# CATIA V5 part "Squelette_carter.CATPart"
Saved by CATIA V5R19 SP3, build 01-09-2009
Part number: Squelette_carter
Bounding box of the stored display mesh (mm): x 0 to 0, y -10 to 300, z -104 to 10
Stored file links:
  C:\Users\Frédéric\Documents\WF\STSCPI 09-11\Projets\Projet multiplicateur eolienne\Maquette eolienne\Squelette_carter.CATPart
  C:\Users\Frédéric\Documents\WF\STSCPI 09-11\Projets\Projet multiplicateur eolienne\Maquette eolienne\Squelette_sortie.CATPart
  C:\Users\Frédéric\Documents\WF\STSCPI 09-11\Projets\Projet multiplicateur eolienne\Maquette eolienne\Squelette_intermediaire.CATPart
  C:\Users\Frédéric\Documents\WF\STSCPI 09-11\Projets\Projet multiplicateur eolienne\Maquette eolienne\Multiplicateur_eolien.CATProduct
  C:\Users\Frédéric\Documents\WF\STSCPI 09-11\Projets\Projet multiplicateur eolienne\Maquette eolienne\Squelette_entree.CATPart
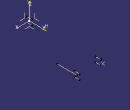
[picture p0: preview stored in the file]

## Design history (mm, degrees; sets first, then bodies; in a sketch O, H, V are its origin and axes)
External parameters (linked from other documents)
  External.Longueur = 18 mm
  External.Longueur.1 = 76 mm
  `External.rayon primitif A et C` = 76 mm
  `External.rayon primitif B et D` = 18 mm
  External.Longueur.2 = 20 mm
AxisSystem1: origin (0, 0, 0), X (1, 0, 0), Y (0, 1, 0), Z (0, 0, 1)
Body1 (main body)
  Sketch1 on YZ plane of AxisSystem1, origin (0, 0, 0), H (0, 1, 0), V (0, 0, 1)
    line L1 (-10, 10) -> (10, 10)
    point P1 (-10, 10)
    line L2 (-10, -10) -> (10, -10)
    point P3 (-10, -10)
    line L3 (270, 10) -> (290, 10)
    point P5 (270, 10)
    line L4 (270, -10) -> (290, -10)
    point P7 (270, -10)
    point P9 (280, 0)
    point P10 (193.8803, -94)
    line L5 (183.8803, -84) -> (203.8803, -84)
    point P11 (183.8803, -84)
    line L6 (183.8803, -104) -> (203.8803, -104)
    point P13 (183.8803, -104)
    point P15 (300, 0)
    line L7 (193.8803, -94) -> (113.8803, -94)
    distance O P15 = 300
    distance P9 P5 H = 10
    distance L3 L4 = 20
    length L4 = 20
    length L3 = 20
    length L5 = 20
    length L6 = 20
    distance P10 L5 = 10
    distance L5 L6 = 20
    distance P11 P10 H = 10
    distance P7 P9 H = 10
    distance P10 P13 H = 10
    length L1 = 20
    length L2 = 20
    distance L1 L2 = 20
    distance O P1 H = 10
    distance O P3 H = 10
    distance P9 L3 = 10
    distance P15 P9 = 20 {= External.Longueur.2}
    distance H P10 = 94 {= `External.rayon primitif A et C` +`External.rayon primitif B et D`}
    horizontal: L1 H, L2 H, L3 H, L4 H, L5 H, L6 H, L7 H
    coincidence: P9 H, P15 H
